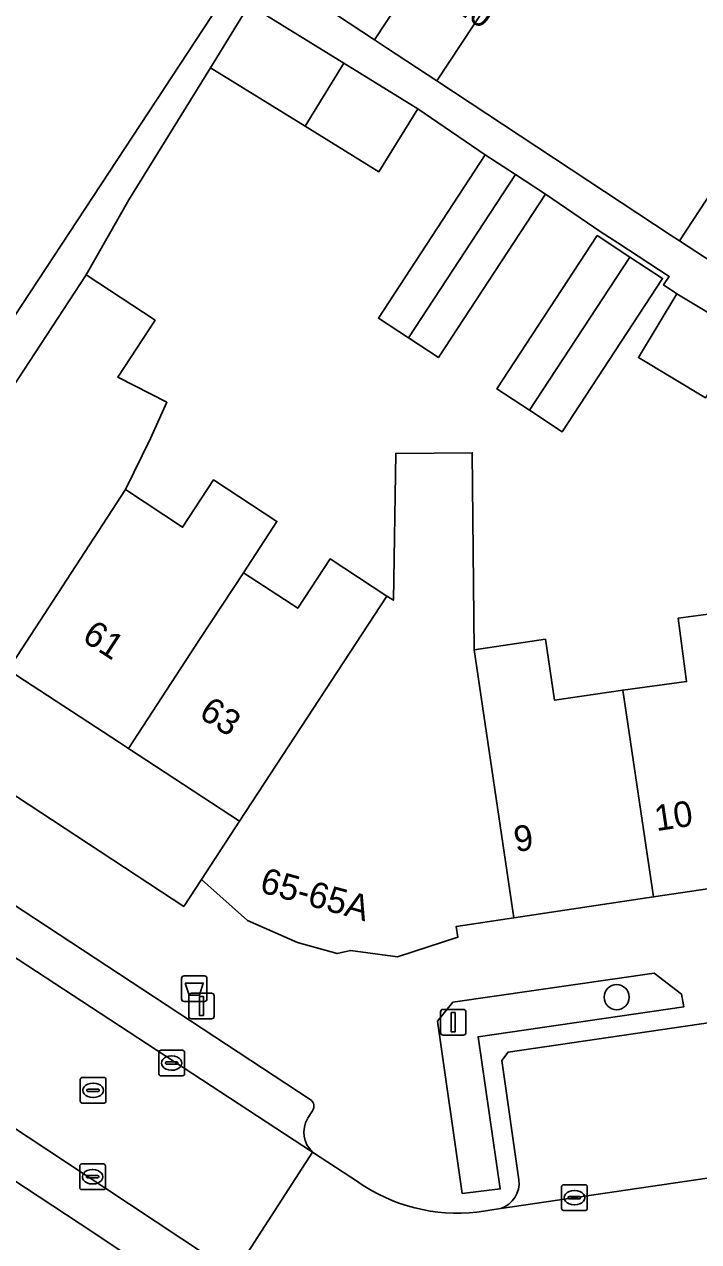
# Model space of a CAD drawing. Extents: x 159279 to 160377, y 384531 to 385888.
# Drawn here: x 159875.06 to 159901.36, y 384960.39 to 385007.87 of the extents above; entities that cross this region are included whole.
import ezdxf

# ---------------------------------------------------------------- set-up
doc = ezdxf.new("R2010")
doc.units = 0
for name, color, linetype in [('IMGEO_Afvalbak', 7, 'Continuous'), ('IMGEO_Boom', 7, 'Continuous'), ('IMGEO_Erf', 7, 'Continuous'), ('IMGEO_Groenvoorziening', 7, 'Continuous'), ('IMGEO_Haag', 7, 'Continuous'), ('IMGEO_Kolk', 7, 'Continuous'), ('IMGEO_Lichtmast', 7, 'Continuous'), ('IMGEO_Pand', 7, 'Continuous'), ('IMGEO_Pand_nummerreeks', 7, 'Continuous'), ('IMGEO_Parkeervlak_open', 7, 'Continuous'), ('IMGEO_Rijbaan_lokaal_open', 7, 'Continuous'), ('IMGEO_Rioolput', 7, 'Continuous'), ('IMGEO_Voetpad_open', 7, 'Continuous')]:
    doc.layers.add(name, color=color, linetype=linetype)

msp = doc.modelspace()

# ---------------------------------------------------------------- linework, layer by layer
at = {"layer": 'IMGEO_Afvalbak'}
for p, q in [((159881.188, 384969.861), (159881.188, 384970.661)), ((159881.188, 384970.661), (159881.188, 384969.861)), ((159881.288, 384970.761), (159882.078, 384970.761)), ((159882.078, 384970.761), (159881.288, 384970.761)), ((159882.178, 384970.661), (159882.178, 384969.861)), ((159882.178, 384969.861), (159882.178, 384970.661)), ((159882.078, 384969.761), (159881.288, 384969.761)), ((159881.288, 384969.761), (159882.078, 384969.761))]:
    msp.add_line(p, q, dxfattribs=at)
msp.add_lwpolyline([(159881.331, 384970.475), (159882.035, 384970.475), (159881.886, 384970.005), (159881.48, 384970.005), (159881.331, 384970.475)], dxfattribs=at)
for centre, start, end in [((159881.288, 384970.661), 90, 180), ((159881.288, 384970.661), 90, 180), ((159882.078, 384970.661), 0, 90), ((159882.078, 384970.661), 360, 90), ((159881.288, 384969.861), 180, 270), ((159881.288, 384969.861), 180, 270), ((159882.078, 384969.861), 270, 0), ((159882.078, 384969.861), 270, 0)]:
    msp.add_arc(centre, 0.1, start, end, dxfattribs=at)
at = {"layer": 'IMGEO_Boom'}
msp.add_circle((159898.161, 384969.928), 0.489, dxfattribs=at)
at = {"layer": 'IMGEO_Erf'}
for points in [[(159849.638, 385008.68), (159851.756, 385007.29), (159853.102, 385009.335), (159855.578, 385007.706), (159858.109, 385006.041), (159856.739, 385003.958), (159858.801, 385002.601), (159860.922, 385001.206), (159862.28, 385003.27), (159864.751, 385001.644), (159867.251, 385000), (159865.953, 384998.027), (159868.048, 384996.653), (159870.394, 384995.109), (159871.69, 384997.08), (159874.036, 384995.536), (159883.282, 385009.593)], [(159901.627, 384993.302), (159899.014, 384994.87), (159900.51, 384997.363), (159899.991, 384997.703), (159900.209, 384998.035), (159898.206, 384999.347), (159897.562, 384999.769), (159895.38, 385001.24), (159891.209, 384994.873), (159890.038, 384995.639), (159888.868, 384996.406), (159893.039, 385002.773), (159890.4, 385004.571), (159888.885, 385002.119), (159886.01, 385003.895), (159882.317, 385006.176), (159879.138, 385001.03), (159877.471, 384998.096), (159880.158, 384996.336), (159878.7, 384994.111), (159880.617, 384993.128), (159879.981, 384991.711), (159879.006, 384989.729), (159881.231, 384988.256), (159882.439, 384990.1), (159884.91, 384988.482), (159883.608, 384986.479), (159885.724, 384985.093), (159886.987, 384987.021), (159889.203, 384985.569), (159889.454, 384985.411), (159889.546, 384991.132), (159892.528, 384991.159), (159892.597, 384983.473), (159895.383, 384983.888), (159895.738, 384981.508), (159898.398, 384981.904), (159900.887, 384982.237), (159900.557, 384984.705), (159903.49, 384985.097)]]:
    msp.add_lwpolyline(points, dxfattribs=at)
for points in [[(159896.035, 384991.982), (159894.761, 384992.816), (159893.488, 384993.651), (159897.403, 384999.628), (159898.677, 384998.793), (159899.951, 384997.959)], [(159874.428, 384982.695), (159874.183, 384982.862), (159869.502, 384985.928), (159867.332, 384982.615), (159881.271, 384973.458), (159881.966, 384974.522), (159883.452, 384976.79), (159879.117, 384979.629), (159878.766, 384979.859)]]:
    msp.add_lwpolyline(points, close=True, dxfattribs=at)
at = {"layer": 'IMGEO_Groenvoorziening'}
msp.add_lwpolyline([(159892.136, 384962.272), (159893.621, 384962.452), (159892.759, 384968.385), (159900.785, 384969.557), (159900.697, 384970.046), (159899.622, 384970.864), (159891.765, 384969.731), (159891.169, 384968.992)], close=True, dxfattribs=at)
at = {"layer": 'IMGEO_Haag'}
msp.add_lwpolyline([(159892.136, 384962.272), (159893.621, 384962.452), (159892.759, 384968.385), (159900.785, 384969.557), (159900.697, 384970.046), (159899.622, 384970.864), (159891.765, 384969.731), (159891.169, 384968.992)], close=True, dxfattribs=at)
at = {"layer": 'IMGEO_Kolk'}
for p, q in [((159880.302, 384966.932), (159880.302, 384967.784)), ((159880.377, 384967.858), (159881.229, 384967.858)), ((159881.303, 384967.784), (159881.303, 384966.932)), ((159880.561, 384967.352), (159880.561, 384967.364)), ((159880.999, 384967.315), (159880.601, 384967.315)), ((159880.604, 384967.401), (159881.002, 384967.401)), ((159880.79, 384967.638), (159880.815, 384967.638)), ((159881.045, 384967.364), (159881.045, 384967.352)), ((159881.229, 384966.858), (159880.377, 384966.858)), ((159880.813, 384967.078), (159880.788, 384967.078)), ((159877.218, 384962.498), (159877.218, 384963.35)), ((159877.293, 384963.424), (159878.145, 384963.424)), ((159877.706, 384963.204), (159877.731, 384963.204)), ((159878.219, 384963.35), (159878.219, 384962.498)), ((159877.477, 384962.918), (159877.477, 384962.93)), ((159877.915, 384962.881), (159877.517, 384962.881)), ((159877.52, 384962.967), (159877.918, 384962.967)), ((159877.729, 384962.644), (159877.704, 384962.644)), ((159877.961, 384962.93), (159877.961, 384962.918)), ((159896.015, 384961.684), (159896.015, 384962.536)), ((159896.09, 384962.61), (159896.942, 384962.61)), ((159897.016, 384962.536), (159897.016, 384961.684)), ((159878.145, 384962.424), (159877.293, 384962.424)), ((159896.274, 384962.104), (159896.274, 384962.116)), ((159896.712, 384962.067), (159896.314, 384962.067)), ((159896.317, 384962.153), (159896.715, 384962.153)), ((159896.503, 384962.39), (159896.528, 384962.39)), ((159896.758, 384962.116), (159896.758, 384962.104)), ((159896.942, 384961.61), (159896.09, 384961.61)), ((159896.526, 384961.83), (159896.501, 384961.83))]:
    msp.add_line(p, q, dxfattribs=at)
for points in [[(159880.302, 384966.932), (159880.302, 384967.784)], [(159880.377, 384967.858), (159881.229, 384967.858)], [(159881.303, 384967.784), (159881.303, 384966.932)], [(159881.229, 384966.858), (159880.377, 384966.858)], [(159877.218, 384962.498), (159877.218, 384963.35)], [(159877.293, 384963.424), (159878.145, 384963.424)], [(159878.219, 384963.35), (159878.219, 384962.498)], [(159896.015, 384961.684), (159896.015, 384962.536)], [(159896.09, 384962.61), (159896.942, 384962.61)], [(159897.016, 384962.536), (159897.016, 384961.684)], [(159878.145, 384962.424), (159877.293, 384962.424)], [(159896.942, 384961.61), (159896.09, 384961.61)]]:
    msp.add_lwpolyline(points, dxfattribs=at)
for centre, radius, start, end in [((159880.379, 384967.782), 0.0765, 91.552, 178.448), ((159880.379, 384967.782), 0.0765, 91.552, 178.448), ((159881.227, 384967.782), 0.0765, 1.552, 88.448), ((159881.227, 384967.782), 0.0765, 1.552, 88.448), ((159880.601, 384967.361), 0.0403, 85.8775, 175.7526), ((159880.598, 384967.351), 0.0366, 178.938, 274.7102), ((159881.002, 384967.358), 0.043, 264.8664, 352.4533), ((159881.006, 384967.363), 0.0386, 1.7309, 96.639), ((159880.379, 384966.934), 0.0765, 181.552, 268.448), ((159880.379, 384966.934), 0.0765, 181.552, 268.448), ((159881.227, 384966.934), 0.0765, 271.552, 358.448), ((159881.227, 384966.934), 0.0765, 271.552, 358.448), ((159877.295, 384963.348), 0.0765, 91.552, 178.448), ((159877.295, 384963.348), 0.0765, 91.552, 178.448), ((159878.143, 384963.348), 0.0765, 1.552, 88.448), ((159878.143, 384963.348), 0.0765, 1.552, 88.448), ((159877.517, 384962.927), 0.0403, 85.8775, 175.7526), ((159877.514, 384962.917), 0.0366, 178.938, 274.7102), ((159877.918, 384962.924), 0.043, 264.8664, 352.4533), ((159877.922, 384962.929), 0.0386, 1.7309, 96.639), ((159896.092, 384962.534), 0.0765, 91.552, 178.448), ((159896.092, 384962.534), 0.0765, 91.552, 178.448), ((159896.94, 384962.534), 0.0765, 1.552, 88.448), ((159896.94, 384962.534), 0.0765, 1.552, 88.448), ((159877.295, 384962.5), 0.0765, 181.552, 268.448), ((159877.295, 384962.5), 0.0765, 181.552, 268.448), ((159878.143, 384962.5), 0.0765, 271.552, 358.448), ((159878.143, 384962.5), 0.0765, 271.552, 358.448), ((159896.314, 384962.113), 0.0403, 85.8775, 175.7526), ((159896.311, 384962.103), 0.0366, 178.938, 274.7102), ((159896.715, 384962.11), 0.043, 264.8664, 352.4533), ((159896.719, 384962.115), 0.0386, 1.7309, 96.639), ((159896.092, 384961.686), 0.0765, 181.552, 268.448), ((159896.092, 384961.686), 0.0765, 181.552, 268.448), ((159896.94, 384961.686), 0.0765, 271.552, 358.448), ((159896.94, 384961.686), 0.0765, 271.552, 358.448)]:
    msp.add_arc(centre, radius, start, end, dxfattribs=at)
for centre, major_axis, ratio, start_param, end_param in [((159880.789, 384967.358), (-0.387, 0.002), 0.722429, 4.712389, 7.853982), ((159880.814, 384967.358), (-0.39, 0.002), 0.717154, 1.570796, 4.712389), ((159877.705, 384962.924), (-0.387, 0.002), 0.722429, 4.712389, 7.853982), ((159877.73, 384962.924), (-0.39, 0.002), 0.717154, 1.570796, 4.712389), ((159896.502, 384962.11), (-0.387, 0.002), 0.722429, 4.712389, 7.853982), ((159896.527, 384962.11), (-0.39, 0.002), 0.717154, 1.570796, 4.712389)]:
    msp.add_ellipse(centre, major_axis=major_axis, ratio=ratio, start_param=start_param, end_param=end_param, dxfattribs=at)
at = {"layer": 'IMGEO_Lichtmast'}
for p, q in [((159881.471, 384969.185), (159881.471, 384969.985)), ((159881.471, 384969.985), (159881.471, 384969.185)), ((159881.571, 384970.085), (159882.361, 384970.085)), ((159882.361, 384970.085), (159881.571, 384970.085)), ((159882.461, 384969.985), (159882.461, 384969.185)), ((159882.461, 384969.185), (159882.461, 384969.985)), ((159891.29, 384968.549), (159891.29, 384969.349)), ((159891.29, 384969.349), (159891.29, 384968.549)), ((159891.39, 384969.449), (159892.18, 384969.449)), ((159892.18, 384969.449), (159891.39, 384969.449)), ((159892.28, 384969.349), (159892.28, 384968.549)), ((159892.28, 384968.549), (159892.28, 384969.349)), ((159882.361, 384969.085), (159881.571, 384969.085)), ((159881.571, 384969.085), (159882.361, 384969.085)), ((159892.18, 384968.449), (159891.39, 384968.449)), ((159891.39, 384968.449), (159892.18, 384968.449))]:
    msp.add_line(p, q, dxfattribs=at)
for points in [[(159881.891, 384969.96), (159882.041, 384969.96), (159882.041, 384969.21), (159881.891, 384969.21), (159881.891, 384969.96)], [(159891.71, 384969.324), (159891.86, 384969.324), (159891.86, 384968.574), (159891.71, 384968.574), (159891.71, 384969.324)]]:
    msp.add_lwpolyline(points, dxfattribs=at)
for centre, start, end in [((159881.571, 384969.985), 90, 180), ((159881.571, 384969.985), 90, 180), ((159882.361, 384969.985), 0, 90), ((159882.361, 384969.985), 360, 90), ((159881.571, 384969.185), 180, 270), ((159881.571, 384969.185), 180, 270), ((159882.361, 384969.185), 270, 0), ((159882.361, 384969.185), 270, 0), ((159891.39, 384969.349), 90, 180), ((159891.39, 384969.349), 90, 180), ((159892.18, 384969.349), 0, 90), ((159892.18, 384969.349), 360, 90), ((159891.39, 384968.549), 180, 270), ((159891.39, 384968.549), 180, 270), ((159892.18, 384968.549), 270, 0), ((159892.18, 384968.549), 270, 0)]:
    msp.add_arc(centre, 0.1, start, end, dxfattribs=at)
at = {"layer": 'IMGEO_Pand'}
for points in [[(159892.032, 385012.298), (159889.603, 385013.9), (159886.287, 385008.871), (159888.716, 385007.269)], [(159894.462, 385010.696), (159891.145, 385005.667), (159900.292, 384999.636), (159900.608, 384999.429), (159901.928, 385001.432), (159905.422, 385006.729), (159905.629, 385007.043), (159901.044, 385014.131), (159894.956, 385010.37)], [(159894.462, 385010.696), (159892.032, 385012.298), (159888.716, 385007.269), (159889.19, 385006.957), (159891.145, 385005.667)], [(159887.524, 385006.348), (159883.832, 385008.629), (159882.317, 385006.176), (159886.01, 385003.895)], [(159890.4, 385004.571), (159887.524, 385006.348), (159886.01, 385003.895), (159888.885, 385002.119)], [(159894.21, 385002.006), (159893.039, 385002.773), (159888.868, 384996.406), (159890.038, 384995.639)], [(159895.38, 385001.24), (159894.21, 385002.006), (159890.038, 384995.639), (159891.209, 384994.873)], [(159908.656, 384996.996), (159903.243, 385000.565), (159901.928, 385001.432), (159900.608, 384999.429), (159901.923, 384998.562), (159904.892, 384996.604), (159907.335, 384994.993)], [(159898.677, 384998.793), (159897.403, 384999.628), (159893.488, 384993.651), (159894.761, 384992.816)], [(159898.677, 384998.793), (159894.761, 384992.816), (159896.035, 384991.982), (159899.951, 384997.959)], [(159880.158, 384996.336), (159877.471, 384998.096), (159869.502, 384985.928), (159874.183, 384982.862), (159874.428, 384982.695), (159879.006, 384989.729), (159879.981, 384991.711), (159880.617, 384993.128), (159878.7, 384994.111)], [(159903.26, 384995.713), (159900.51, 384997.363), (159899.014, 384994.87), (159901.627, 384993.302)], [(159892.597, 384983.473), (159892.528, 384991.159), (159889.546, 384991.132), (159889.454, 384985.411), (159889.203, 384985.569), (159883.452, 384976.79), (159881.966, 384974.522), (159883.758, 384972.92), (159885.71, 384972.055), (159887.26, 384971.63), (159887.776, 384971.753), (159889.615, 384971.505), (159891.971, 384972.266), (159891.907, 384972.69), (159894.155, 384973.026)], [(159883.608, 384986.479), (159884.91, 384988.482), (159882.439, 384990.1), (159881.231, 384988.256), (159879.006, 384989.729), (159874.428, 384982.695), (159878.766, 384979.859), (159879.117, 384979.629), (159881.917, 384983.912)], [(159889.203, 384985.569), (159886.987, 384987.021), (159885.724, 384985.093), (159883.608, 384986.479), (159881.917, 384983.912), (159879.117, 384979.629), (159883.452, 384976.79)], [(159903.49, 384985.097), (159900.557, 384984.705), (159900.887, 384982.237), (159898.398, 384981.904), (159899.601, 384973.838), (159905.048, 384974.65)], [(159898.398, 384981.904), (159895.738, 384981.508), (159895.383, 384983.888), (159892.597, 384983.473), (159894.155, 384973.026), (159899.601, 384973.838)]]:
    msp.add_lwpolyline(points, close=True, dxfattribs=at)
at = {"layer": 'IMGEO_Parkeervlak_open'}
for points in [[(159886.212, 384965.938), (159840.92, 384995.697), (159839.936, 384994.206), (159886.296, 384963.889)], [(159883.239, 384959.155), (159878.161, 384962.52), (159836.97, 384989.714), (159835.989, 384988.228), (159877.228, 384961.089), (159881.322, 384958.367)], [(159911.837, 384965.373), (159911.146, 384969.991), (159910.777, 384970.248), (159893.929, 384967.785), (159893.677, 384967.458), (159894.35, 384962.801)], [(159886.105, 384965.19), (159886.298, 384965.49)], [(159893.64, 384961.687), (159912.925, 384964.521)]]:
    msp.add_lwpolyline(points, dxfattribs=at)
for centre, radius, start, end in [((159886.029, 384965.671), 0.324, 326.1817, 55.5514), ((159887.017, 384964.659), 1.055, 149.797, 226.9068), ((159893.302, 384962.686), 1.055, 288.7098, 6.268)]:
    msp.add_arc(centre, radius, start, end, dxfattribs=at)
at = {"layer": 'IMGEO_Rijbaan_lokaal_open'}
msp.add_lwpolyline([(159886.296, 384963.889), (159839.936, 384994.206), (159836.97, 384989.714), (159878.161, 384962.52), (159883.239, 384959.155)], close=True, dxfattribs=at)
for points in [[(159914.051, 384964.67), (159912.925, 384964.521), (159893.64, 384961.687), (159892.709, 384961.547)], [(159888.085, 384962.714), (159886.296, 384963.889), (159883.239, 384959.155), (159884.146, 384958.55)]]:
    msp.add_lwpolyline(points, dxfattribs=at)
msp.add_arc((159891.944, 384968.262), 6.758, 235.1756, 276.4955, dxfattribs=at)
at = {"layer": 'IMGEO_Rioolput'}
for p, q in [((159877.312, 384966.795), (159878.164, 384966.795)), ((159877.237, 384965.869), (159877.237, 384966.721)), ((159877.539, 384966.338), (159877.937, 384966.338)), ((159877.725, 384966.575), (159877.75, 384966.575)), ((159878.238, 384966.721), (159878.238, 384965.869)), ((159877.496, 384966.289), (159877.496, 384966.301)), ((159877.934, 384966.252), (159877.536, 384966.252)), ((159877.748, 384966.015), (159877.723, 384966.015)), ((159877.98, 384966.301), (159877.98, 384966.289)), ((159878.164, 384965.795), (159877.312, 384965.795))]:
    msp.add_line(p, q, dxfattribs=at)
for points in [[(159877.312, 384966.795), (159878.164, 384966.795)], [(159877.237, 384965.869), (159877.237, 384966.721)], [(159878.238, 384966.721), (159878.238, 384965.869)], [(159878.164, 384965.795), (159877.312, 384965.795)]]:
    msp.add_lwpolyline(points, dxfattribs=at)
for centre, radius, start, end in [((159877.314, 384966.719), 0.0765, 91.552, 178.448), ((159877.314, 384966.719), 0.0765, 91.552, 178.448), ((159878.162, 384966.719), 0.0765, 1.552, 88.448), ((159878.162, 384966.719), 0.0765, 1.552, 88.448), ((159877.536, 384966.298), 0.0403, 85.8775, 175.7526), ((159877.941, 384966.3), 0.0386, 1.7309, 96.639), ((159877.314, 384965.871), 0.0765, 181.552, 268.448), ((159877.314, 384965.871), 0.0765, 181.552, 268.448), ((159877.533, 384966.288), 0.0366, 178.938, 274.7102), ((159877.937, 384966.295), 0.043, 264.8664, 352.4533), ((159878.162, 384965.871), 0.0765, 271.552, 358.448), ((159878.162, 384965.871), 0.0765, 271.552, 358.448)]:
    msp.add_arc(centre, radius, start, end, dxfattribs=at)
for centre, major_axis, ratio, start_param, end_param in [((159877.724, 384966.295), (-0.387, 0.002), 0.722429, 4.712389, 7.853982), ((159877.749, 384966.295), (-0.39, 0.002), 0.717154, 1.570796, 4.712389)]:
    msp.add_ellipse(centre, major_axis=major_axis, ratio=ratio, start_param=start_param, end_param=end_param, dxfattribs=at)
at = {"layer": 'IMGEO_Voetpad_open'}
for points in [[(159922.182, 384975.286), (159922.705, 384976.055), (159919.321, 384978.411), (159919.24, 384978.293), (159918.09, 384976.595), (159910.495, 384975.462), (159905.048, 384974.65), (159899.601, 384973.838), (159894.155, 384973.026), (159891.907, 384972.69), (159891.971, 384972.266), (159889.615, 384971.505), (159887.776, 384971.753), (159887.26, 384971.63), (159885.71, 384972.055), (159883.758, 384972.92), (159881.966, 384974.522), (159881.271, 384973.458), (159867.332, 384982.615), (159866.078, 384983.439), (159840.869, 385000), (159815.287, 385016.806)], [(159817.889, 385010.811), (159834.363, 385000), (159838.529, 384997.266), (159840.92, 384995.697), (159886.212, 384965.938)], [(159883.282, 385009.593), (159874.036, 384995.536)], [(159869.502, 384985.928), (159877.471, 384998.096), (159879.138, 385001.03), (159882.317, 385006.176), (159883.832, 385008.629), (159887.524, 385006.348), (159890.4, 385004.571), (159893.039, 385002.773), (159894.21, 385002.006), (159895.38, 385001.24), (159897.562, 384999.769), (159898.206, 384999.347), (159900.209, 384998.035), (159899.991, 384997.703), (159900.51, 384997.363), (159903.26, 384995.713)], [(159901.923, 384998.562), (159900.608, 384999.429), (159900.292, 384999.636), (159891.145, 385005.667), (159889.19, 385006.957), (159888.716, 385007.269), (159886.287, 385008.871)], [(159881.322, 384958.367), (159877.228, 384961.089), (159835.989, 384988.228), (159833.608, 384989.793), (159818.079, 385000), (159812.281, 385003.811), (159811.878, 385004.067)], [(159894.35, 384962.801), (159893.677, 384967.458), (159893.929, 384967.785), (159910.777, 384970.248), (159911.146, 384969.991), (159911.837, 384965.373)], [(159886.298, 384965.49), (159886.105, 384965.19)], [(159886.296, 384963.889), (159888.085, 384962.714)], [(159892.709, 384961.547), (159893.64, 384961.687)]]:
    msp.add_lwpolyline(points, dxfattribs=at)
msp.add_lwpolyline([(159891.169, 384968.992), (159891.765, 384969.731), (159899.622, 384970.864), (159900.697, 384970.046), (159900.785, 384969.557), (159892.759, 384968.385), (159893.621, 384962.452), (159892.136, 384962.272)], close=True, dxfattribs=at)
for centre, radius, start, end in [((159886.029, 384965.671), 0.324, 326.1817, 55.5514), ((159887.017, 384964.659), 1.055, 149.797, 226.9068), ((159891.944, 384968.262), 6.758, 235.1756, 276.4955), ((159893.302, 384962.686), 1.055, 288.7098, 6.268)]:
    msp.add_arc(centre, radius, start, end, dxfattribs=at)

# ---------------------------------------------------------------- texts
at = {"layer": 'IMGEO_Pand_nummerreeks'}
for s, rotation, p in [('33/G10', 326.5221, (159889.288, 385010.08)), ('61', 326.7742, (159877.261, 384983.858)), ('63', 326.7742, (159881.817, 384980.873)), ('10', 8.4798, (159899.713, 384976.402)), ('9', 8.4798, (159894.229, 384975.585)), ('65-65A', 344.4385, (159884.194, 384974.038))]:
    msp.add_text(s, height=1, rotation=rotation, dxfattribs=at).set_placement(p)

doc.saveas('drawing.dxf')
